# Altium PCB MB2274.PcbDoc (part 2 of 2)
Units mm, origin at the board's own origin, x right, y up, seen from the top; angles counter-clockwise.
Board outline 127 x 73 mm, 4 copper layers (Top Layer, Signal Layer 1, Signal Layer 2, Bottom Layer), stack 1.49 mm thick; 50 components, 79 nets, 284 pads, 1052 vias.
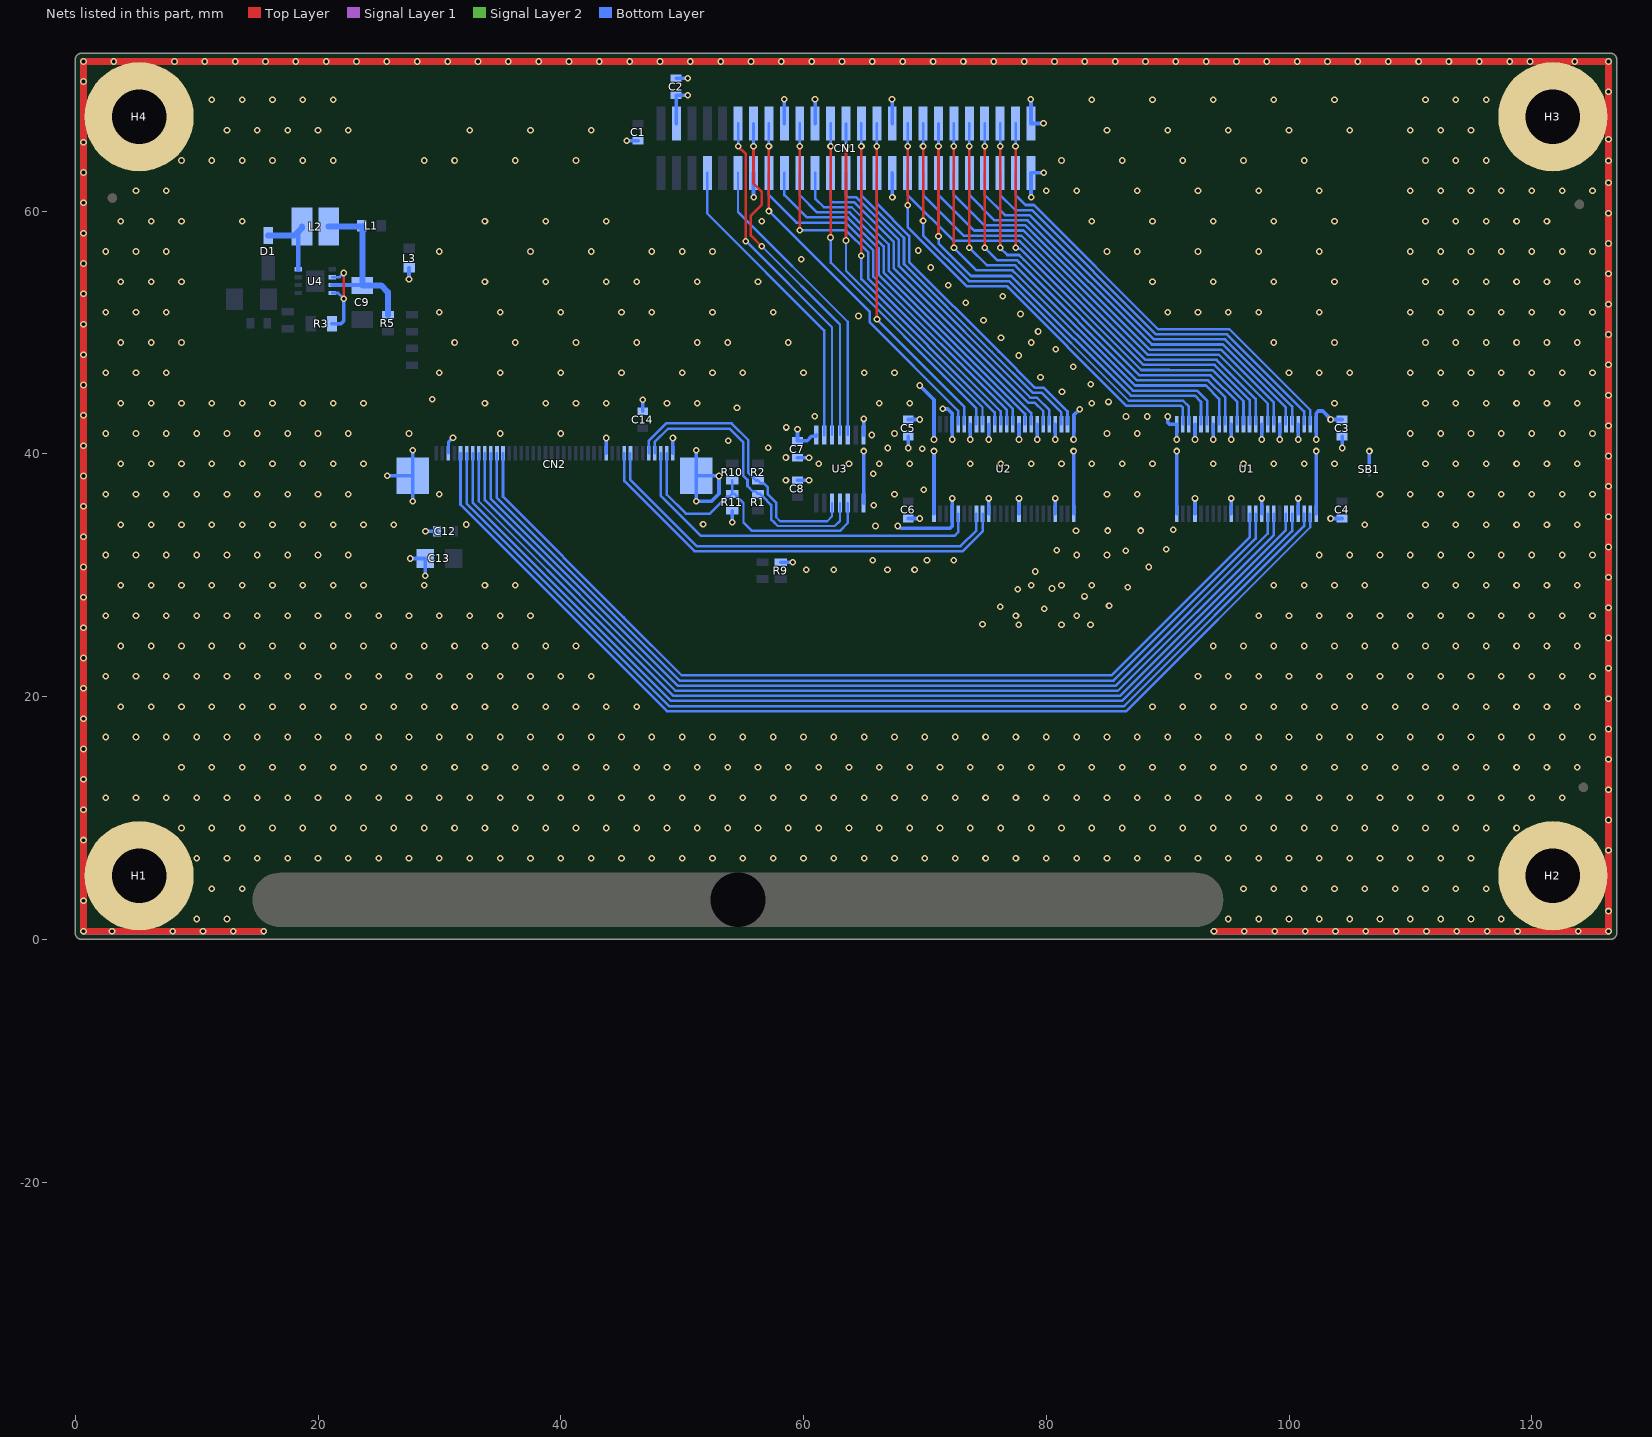
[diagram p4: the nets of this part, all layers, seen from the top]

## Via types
v1: diameter 0.55, hole 0.3, Top Layer to Bottom Layer, 1052 vias

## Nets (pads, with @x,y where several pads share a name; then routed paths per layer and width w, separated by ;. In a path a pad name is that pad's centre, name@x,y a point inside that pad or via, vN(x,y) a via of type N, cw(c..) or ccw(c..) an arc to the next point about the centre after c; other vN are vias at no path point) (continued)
GND: C1.1 C2.1 C3.1 C4.1 C5.1 C6.1 C7.1 C8.1 C12.1 C13.2 C14.1 CN1.1 CN1.2 CN1.19 CN1.20 CN1.30 CN1.34 CN1.37 CN2.1 CN2.12 CN2.38 CN2.MP1 CN2.MP2 H1.1 H2.1 H3.1 H4.1 L3.1 R9.1 R11.1 U1.4 U1.10 U1.15 U1.21 U1.25 U1.28 U1.34 U1.39 U1.45 U1.48 U2.4 U2.10 U2.15 U2.21 U2.25 U2.28 U2.34 U2.39 U2.45 U2.48 U3.7 | length 1377.9
  Top Layer w0.55: H1.1@5.26,5.23 5.375,5.115 5.375,0.997 5.053,0.675 ; v1(15.525,0.675) 5.053,0.675 ; v1(93.825,0.675) v1(108.825,0.675) v1(111.325,0.675) v1(126.325,0.675) v1(126.325,7.325) v1(126.325,9.825) 126.325,11.95 v1(126.325,42.325) v1(126.325,44.825) 126.325,71.43 v1(126.325,72.325) v1(20.675,72.325) v1(0.675,72.325) v1(0.675,28.175) v1(0.675,25.675) v1(0.675,23.175) v1(0.675,20.675) v1(0.675,18.175) v1(0.675,15.675) v1(0.675,13.175) v1(0.675,10.675) v1(0.675,8.175) v1(0.675,3.175) v1(0.675,0.675) 5.053,0.675
  Signal Layer 1 w0.55: H1.1@5.26,5.23 5.375,5.115 5.375,0.997 5.053,0.675 ; v1(15.525,0.675) 5.053,0.675 ; v1(93.825,0.675) v1(108.825,0.675) v1(111.325,0.675) v1(126.325,0.675) v1(126.325,7.325) v1(126.325,9.825) 126.325,11.95 v1(126.325,42.325) v1(126.325,44.825) 126.325,71.43 v1(126.325,72.325) v1(35.675,72.325) v1(0.675,72.325) v1(0.675,28.175) v1(0.675,25.675) v1(0.675,23.175) v1(0.675,20.675) v1(0.675,18.175) v1(0.675,15.675) v1(0.675,13.175) v1(0.675,10.675) v1(0.675,8.175) v1(0.675,3.175) v1(0.675,0.675) 5.053,0.675
  Signal Layer 2 w0.55: H1.1@5.26,5.23 5.375,5.115 5.375,0.997 5.053,0.675 ; v1(15.525,0.675) 5.053,0.675 ; v1(93.825,0.675) v1(108.825,0.675) v1(111.325,0.675) v1(126.325,0.675) v1(126.325,7.325) v1(126.325,9.825) 126.325,11.95 v1(126.325,42.325) v1(126.325,44.825) 126.325,71.43 v1(126.325,72.325) v1(0.675,72.325) v1(0.675,28.175) v1(0.675,25.675) v1(0.675,23.175) v1(0.675,20.675) v1(0.675,18.175) v1(0.675,15.675) v1(0.675,13.175) v1(0.675,10.675) v1(0.675,8.175) v1(0.675,3.175) v1(0.675,0.675) 5.053,0.675
  Bottom Layer w0.25: CN2.38@30.74,40.05 30.74,40.95 v1(31.115,41.325)
  Bottom Layer w0.3: v1(25.7,38.195) 25.705,38.19 CN2.MP2@27.81,38.19 ; v1(27.5,54.375) L3.1@27.5,55.325 ; v1(27.6,31.375) C13.2@28.825,31.375 v1(28.825,29.95) ; v1(27.805,36.08) 27.81,36.085 CN2.MP2@27.81,38.19 ; v1(27.815,40.3) 27.81,40.295 CN2.MP2@27.81,38.19 ; v1(28.85,33.625) C12.1@29.8,33.625 ; CN2.12@43.74,40.05 v1@43.74,41.225 ; v1(45.425,65.8) C1.1@46.375,65.8 ; C14.1@46.75,43.513 v1(46.75,44.463) ; CN2.1@49.24,40.05 v1@49.24,41.225 ; C2.1@49.5,70.95 v1(50.45,70.95) ; v1(51.175,40.3) 51.17,40.295 CN2.MP1@51.17,38.19 ; v1(54.125,34.35) R11.1@54.125,35.3 ; CN1.37@55.88,63.147 55.88,61.154 v1(55.895,61.139) ; R9.1@58.125,31.075 v1(59.11,31.075) ; v1(58.405,69.225) 58.42,69.21 CN1.34@58.42,67.217 ; C8.1@59.5,37.825 v1(60.45,37.825) ; C7.1@59.5,39.675 v1(60.45,39.675) ; v1(60.945,69.225) 60.96,69.21 CN1.30@60.96,67.217 ; U3.7@64.95,41.55 v1@64.95,42.8 ; v1(67.295,69.225) 67.31,69.21 CN1.20@67.31,67.217 ; CN1.19@67.31,63.147 67.31,61.154 v1(67.325,61.139) ; v1(67.775,34.05) 67.843,34.05 68.018,33.875 72.075,33.875 72.25,34.05 U2.21@72.25,35.075 v1(72.25,36.325) ; C6.1@68.625,34.675 v1(69.575,34.675) ; C5.1@68.625,42.825 v1(69.575,42.825) ; v1(69.575,45.625) 70.75,44.45 U2.25@70.75,42.425 v1(70.75,41.175) ; v1(71.475,43.725) 71.507,43.693 71.882,43.693 72.25,43.325 v1(72.25,41.175) ; U2.15@75.25,35.075 v1(75.25,36.325) ; v1(75.25,41.175) U2.34@75.25,42.425 ; U2.10@77.75,35.075 v1(77.75,36.325) ; v1(77.75,41.175) U2.39@77.75,42.425 ; v1(78.725,69.225) 78.74,69.21 CN1.2@78.74,67.217 79.767,67.217 v1(79.775,67.225) ; v1(78.755,61.139) 78.74,61.154 CN1.1@78.74,63.147 79.797,63.147 v1(79.8,63.15) ; U2.4@80.75,35.075 v1(80.75,36.325) ; v1(80.75,41.175) U2.45@80.75,42.425 ; v1(82.25,41.175) U2.48@82.25,42.425 82.25,43.175 v1(82.75,43.675) ; v1(90,43.075) 90,42.574 90.149,42.425 U1.25@90.75,42.425 v1(90.75,41.175) ; U1.21@92.25,35.075 v1(92.25,36.325) ; v1(92.25,41.175) U1.28@92.25,42.425 ; U1.15@95.25,35.075 v1(95.25,36.325) ; v1(95.25,41.175) U1.34@95.25,42.425 ; U1.10@97.75,35.075 v1(97.75,36.325) ; v1(97.75,41.175) U1.39@97.75,42.425 ; U1.4@100.75,35.075 v1(100.75,36.325) ; v1(100.75,41.175) U1.45@100.75,42.425 ; v1(102.25,41.175) U1.48@102.25,42.425 102.25,43.35 102.425,43.525 102.775,43.525 103.425,42.875 v1(103.425,42.825) C3.1@104.375,42.825 ; v1(103.425,34.675) C4.1@104.375,34.675 ; CN2.MP1@51.17,38.19 51.17,36.085 v1(51.165,36.08) 52.405,36.08 53.04,36.715 v1(53.04,38.175) 53.025,38.19 CN2.MP1@51.17,38.19
  Bottom Layer w0.55: H1.1@5.26,5.23 5.375,5.115 5.375,0.997 5.053,0.675 ; v1(15.525,0.675) 5.053,0.675 ; v1(93.825,0.675) v1(108.825,0.675) v1(111.325,0.675) v1(126.325,0.675) v1(126.325,7.325) v1(126.325,9.825) 126.325,11.95 v1(126.325,42.325) v1(126.325,44.825) 126.325,71.43 v1(126.325,72.325) v1(0.675,72.325) v1(0.675,28.175) v1(0.675,25.675) v1(0.675,23.175) v1(0.675,20.675) v1(0.675,18.175) v1(0.675,15.675) v1(0.675,13.175) v1(0.675,10.675) v1(0.675,8.175) v1(0.675,3.175) v1(0.675,0.675) 5.053,0.675
  other v1: 3.025,0.675 8.025,0.675 10.525,0.675 13.025,0.675 96.325,0.675 98.825,0.675 101.325,0.675 103.825,0.675 106.325,0.675 113.825,0.675 116.325,0.675 118.825,0.675 123.825,0.675 10,1.669 12.5,1.669 95,1.669 97.5,1.669 100,1.669 102.5,1.669 105,1.669 107.5,1.669 110,1.669 112.5,1.669 115,1.669 117.5,1.669 126.325,2.325 11.25,4.169 13.75,4.169 96.25,4.169 98.75,4.169 101.25,4.169 103.75,4.169 106.25,4.169 108.75,4.169 111.25,4.169 113.75,4.169 116.25,4.169 10,6.669 12.5,6.669 15,6.669 17.5,6.669 20,6.669 22.5,6.669 25,6.669 27.5,6.669 30,6.669 32.5,6.669 35,6.669 37.5,6.669 40,6.669 42.5,6.669 45,6.669 47.5,6.669 50,6.669 52.5,6.669 55,6.669 57.5,6.669 60,6.669 62.5,6.669 65,6.669 67.5,6.669 70,6.669 72.5,6.669 75,6.669 77.5,6.669 80,6.669 82.5,6.669 85,6.669 87.5,6.669 90,6.669 92.5,6.669 95,6.669 97.5,6.669 100,6.669 102.5,6.669 105,6.669 107.5,6.669 110,6.669 112.5,6.669 115,6.669 8.75,9.169 11.25,9.169 13.75,9.169 16.25,9.169 18.75,9.169 21.25,9.169 23.75,9.169 26.25,9.169 28.75,9.169 31.25,9.169 33.75,9.169 36.25,9.169 38.75,9.169 41.25,9.169 43.75,9.169 46.25,9.169 48.75,9.169 51.25,9.169 53.75,9.169 56.25,9.169 58.75,9.169 61.25,9.169 63.75,9.169 66.25,9.169 68.75,9.169 71.25,9.169 73.75,9.169 76.25,9.169 78.75,9.169 81.25,9.169 83.75,9.169 86.25,9.169 88.75,9.169 91.25,9.169 93.75,9.169 96.25,9.169 98.75,9.169 101.25,9.169 103.75,9.169 106.25,9.169 108.75,9.169 111.25,9.169 113.75,9.169 116.25,9.169 118.75,9.169 2.5,11.669 5,11.669 7.5,11.669 10,11.669 12.5,11.669 15,11.669 17.5,11.669 20,11.669 22.5,11.669 25,11.669 27.5,11.669 30,11.669 32.5,11.669 35,11.669 37.5,11.669 40,11.669 42.5,11.669 45,11.669 47.5,11.669 50,11.669 52.5,11.669 55,11.669 57.5,11.669 60,11.669 62.5,11.669 65,11.669 67.5,11.669 70,11.669 72.5,11.669 75,11.669 77.5,11.669 80,11.669 82.5,11.669 85,11.669 87.5,11.669 90,11.669 92.5,11.669 95,11.669 97.5,11.669 100,11.669 102.5,11.669 105,11.669 107.5,11.669 110,11.669 112.5,11.669 115,11.669 117.5,11.669 120,11.669 122.5,11.669 126.325,12.325 8.75,14.169 11.25,14.169 13.75,14.169 16.25,14.169 18.75,14.169 21.25,14.169 23.75,14.169 26.25,14.169 28.75,14.169 31.25,14.169 33.75,14.169 36.25,14.169 38.75,14.169 41.25,14.169 43.75,14.169 46.25,14.169 48.75,14.169 51.25,14.169 53.75,14.169 56.25,14.169 58.75,14.169 61.25,14.169 63.75,14.169 66.25,14.169 68.75,14.169 71.25,14.169 73.75,14.169 76.25,14.169 78.75,14.169 81.25,14.169 83.75,14.169 86.25,14.169 88.75,14.169 91.25,14.169 93.75,14.169 96.25,14.169 98.75,14.169 101.25,14.169 103.75,14.169 106.25,14.169 108.75,14.169 111.25,14.169 113.75,14.169 116.25,14.169 118.75,14.169 121.25,14.169 123.75,14.169 126.325,14.825 2.5,16.669 5,16.669 7.5,16.669 10,16.669 12.5,16.669 15,16.669 17.5,16.669 20,16.669 22.5,16.669 25,16.669 27.5,16.669 30,16.669 32.5,16.669 35,16.669 37.5,16.669 40,16.669 42.5,16.669 45,16.669 47.5,16.669 50,16.669 52.5,16.669 55,16.669 57.5,16.669 60,16.669 62.5,16.669 65,16.669 67.5,16.669 70,16.669 72.5,16.669 75,16.669 77.5,16.669 80,16.669 82.5,16.669 85,16.669 87.5,16.669 90,16.669 92.5,16.669 95,16.669 97.5,16.669 100,16.669 102.5,16.669 105,16.669 107.5,16.669 110,16.669 112.5,16.669 115,16.669 117.5,16.669 120,16.669 122.5,16.669 125,16.669 126.325,17.325 3.75,19.169 6.25,19.169 8.75,19.169 11.25,19.169 13.75,19.169 16.25,19.169 18.75,19.169 21.25,19.169 23.75,19.169 26.25,19.169 28.75,19.169 31.25,19.169 33.75,19.169 36.25,19.169 38.75,19.169 41.25,19.169 43.75,19.169 46.25,19.169 88.75,19.169 91.25,19.169 93.75,19.169 96.25,19.169 98.75,19.169 101.25,19.169 103.75,19.169 106.25,19.169 108.75,19.169 111.25,19.169 113.75,19.169 116.25,19.169 118.75,19.169 121.25,19.169 123.75,19.169 126.325,19.825 2.5,21.669 5,21.669 7.5,21.669 10,21.669 12.5,21.669 15,21.669 17.5,21.669 20,21.669 22.5,21.669 25,21.669 27.5,21.669 30,21.669 32.5,21.669 35,21.669 37.5,21.669 40,21.669 42.5,21.669 92.5,21.669 95,21.669 97.5,21.669 100,21.669 102.5,21.669 105,21.669 107.5,21.669 110,21.669 112.5,21.669 115,21.669 117.5,21.669 120,21.669 122.5,21.669 125,21.669 126.325,22.325 3.75,24.169 6.25,24.169 8.75,24.169 11.25,24.169 13.75,24.169 16.25,24.169 18.75,24.169 21.25,24.169 23.75,24.169 26.25,24.169 28.75,24.169 31.25,24.169 33.75,24.169 36.25,24.169 38.75,24.169 41.25,24.169 93.75,24.169 96.25,24.169 98.75,24.169 101.25,24.169 103.75,24.169 106.25,24.169 108.75,24.169 111.25,24.169 113.75,24.169 116.25,24.169 118.75,24.169 121.25,24.169 123.75,24.169 126.325,24.825 77.725,25.925 81.25,25.925 83.65,25.925 74.75,25.95 2.5,26.669 5,26.669 7.5,26.669 10,26.669 12.5,26.669 15,26.669 17.5,26.669 20,26.669 22.5,26.669 25,26.669 27.5,26.669 30,26.669 32.5,26.669 35,26.669 37.5,26.669 77.5,26.669 82.5,26.669 97.5,26.669 100,26.669 102.5,26.669 105,26.669 107.5,26.669 110,26.669 112.5,26.669 115,26.669 117.5,26.669 120,26.669 122.5,26.669 125,26.669 79.835,27.236 126.325,27.325 76.2,27.4 85.175,27.475 83.15,28.25 77.65,28.85 80.475,28.9 86.725,29 3.75,29.169 6.25,29.169 8.75,29.169 11.25,29.169 13.75,29.169 16.25,29.169 18.75,29.169 21.25,29.169 23.75,29.169 28.75,29.169 33.75,29.169 36.25,29.169 78.75,29.169 81.25,29.169 83.75,29.169 98.75,29.169 101.25,29.169 103.75,29.169 106.25,29.169 111.25,29.169 113.75,29.169 116.25,29.169 118.75,29.169 121.25,29.169 123.75,29.169 126.325,29.825 79.1,30.3 60.225,30.45 62.5,30.45 66.925,30.45 69.15,30.45 0.675,30.675 88.45,30.675 65.7,31.225 70.175,31.225 72.375,31.225 2.5,31.669 5,31.669 7.5,31.669 10,31.669 12.5,31.669 15,31.669 17.5,31.669 20,31.669 22.5,31.669 82.5,31.669 85,31.669 102.5,31.669 105,31.669 107.5,31.669 110,31.669 112.5,31.669 115,31.669 117.5,31.669 120,31.669 122.5,31.669 125,31.669 86.55,32.025 80.875,32.05 89.875,32.125 126.325,32.325 0.675,33.175 82.45,33.65 85.075,33.675 87.775,33.675 90.45,33.75 65.925,34.05 3.75,34.169 6.25,34.169 8.75,34.169 11.25,34.169 13.75,34.169 16.25,34.169 18.75,34.169 21.25,34.169 23.75,34.169 26.25,34.169 32.2,34.175 106.25,34.169 111.25,34.169 113.75,34.169 116.25,34.169 118.75,34.169 121.25,34.169 123.75,34.169 51.725,34.2 126.325,34.825 0.675,35.675 65.775,35.775 2.5,36.669 5,36.669 7.5,36.669 10,36.669 12.5,36.669 15,36.669 17.5,36.669 20,36.669 22.5,36.669 30,36.669 67.5,36.669 85,36.669 87.5,36.669 107.5,36.669 110,36.669 112.5,36.669 115,36.669 117.5,36.669 120,36.669 122.5,36.669 125,36.669 69.9,37.05 126.325,37.325 58.55,37.825 0.675,38.175 65.75,38.35 3.75,39.169 6.25,39.169 8.75,39.169 11.25,39.169 13.75,39.169 16.25,39.169 18.75,39.169 21.25,39.169 23.75,39.169 61.25,39.169 63.75,39.169 66.25,39.169 68.75,39.169 73.75,39.169 76.25,39.169 78.75,39.169 81.25,39.169 83.75,39.169 86.25,39.169 88.75,39.169 93.75,39.169 96.25,39.169 98.75,39.169 101.25,39.169 103.75,39.169 111.25,39.169 113.75,39.169 116.25,39.169 118.75,39.169 121.25,39.169 123.75,39.169 58.55,39.7 126.325,39.825 69.775,40.425 66.95,40.475 57.1,40.5 0.675,40.675 53.8,41.075 43.74,41.3 49.24,41.3 65.625,41.55 2.5,41.669 5,41.669 7.5,41.669 10,41.669 12.5,41.669 15,41.669 17.5,41.669 20,41.669 22.5,41.669 27.5,41.669 35,41.669 40,41.669 67.5,41.669 85,41.669 87.5,41.669 110,41.669 112.5,41.669 115,41.669 117.5,41.669 120,41.669 122.5,41.669 125,41.669 58.575,42.175 64.95,42.875 86.575,43.075 88.325,43.075 60.925,43.1 0.675,43.175 54.525,43.8 3.75,44.169 6.25,44.169 8.75,44.169 11.25,44.169 13.75,44.169 16.25,44.169 18.75,44.169 21.25,44.169 23.75,44.169 33.75,44.169 38.75,44.169 41.25,44.169 43.75,44.169 48.75,44.169 51.25,44.169 66.25,44.169 68.75,44.169 83.75,44.169 103.75,44.169 111.25,44.169 113.75,44.169 116.25,44.169 118.75,44.169 121.25,44.169 123.75,44.169 85.125,44.275 29.4,44.5 81.3,45.125 0.675,45.675 83.675,45.725 79.525,46.3 2.5,46.669 5,46.669 7.5,46.669 30,46.669 35,46.669 40,46.669 45,46.669 50,46.669 52.5,46.669 55,46.669 60,46.669 65,46.669 67.5,46.669 100,46.669 102.5,46.669 105,46.669 110,46.669 112.5,46.669 115,46.669 117.5,46.669 120,46.669 122.5,46.669 125,46.669 82.225,47.175 126.325,47.325 77.725,48.1 0.675,48.175 80.775,48.625 3.75,49.169 6.25,49.169 8.75,49.169 31.25,49.169 36.25,49.169 41.25,49.169 46.25,49.169 51.25,49.169 53.75,49.169 58.75,49.169 78.75,49.169 98.75,49.169 103.75,49.169 111.25,49.169 113.75,49.169 116.25,49.169 118.75,49.169 121.25,49.169 123.75,49.169 76.275,49.55 126.325,49.825 79.325,50.075 0.675,50.675 74.825,51 64.525,51.35 77.875,51.525 2.5,51.669 5,51.669 7.5,51.669 30,51.669 35,51.669 40,51.669 45,51.669 47.5,51.669 52.5,51.669 57.5,51.669 90,51.669 92.5,51.669 95,51.669 97.5,51.669 102.5,51.669 110,51.669 112.5,51.669 115,51.669 117.5,51.669 120,51.669 122.5,51.669 125,51.669 126.325,52.325 73.375,52.45 76.425,52.975 0.675,53.175 71.925,53.9 3.75,54.169 6.25,54.169 8.75,54.169 33.75,54.169 38.75,54.169 43.75,54.169 46.25,54.169 51.25,54.169 56.25,54.169 88.75,54.169 93.75,54.169 98.75,54.169 103.75,54.169 111.25,54.169 113.75,54.169 116.25,54.169 118.75,54.169 121.25,54.169 123.75,54.169 126.325,54.825 70.475,55.35 0.675,55.675 59.8,56.025 2.5,56.669 5,56.669 7.5,56.669 30,56.669 37.5,56.669 42.5,56.669 47.5,56.669 50,56.669 52.5,56.669 85,56.669 87.5,56.669 92.5,56.669 97.5,56.669 102.5,56.669 110,56.669 112.5,56.669 115,56.669 117.5,56.669 120,56.669 122.5,56.669 125,56.669 69.45,56.75 126.325,57.325 0.675,58.175 56.55,59.15 3.75,59.169 6.25,59.169 8.75,59.169 13.75,59.169 33.75,59.169 38.75,59.169 43.75,59.169 83.75,59.169 88.75,59.169 93.75,59.169 98.75,59.169 103.75,59.169 111.25,59.169 113.75,59.169 116.25,59.169 118.75,59.169 121.25,59.169 126.325,59.825 0.675,60.675 5,61.669 7.5,61.669 80,61.669 82.5,61.669 87.5,61.669 92.5,61.669 97.5,61.669 102.5,61.669 110,61.669 112.5,61.669 115,61.669 117.5,61.669 120,61.669 122.5,61.669 125,61.669 126.325,62.325 0.675,63.175 126.325,64.15 8.75,64.169 11.25,64.169 13.75,64.169 16.25,64.169 18.75,64.169 21.25,64.169 28.75,64.169 31.25,64.169 36.25,64.169 41.25,64.169 81.25,64.169 86.25,64.169 91.25,64.169 96.25,64.169 101.25,64.169 111.25,64.169 113.75,64.169 116.25,64.169 0.675,65.675 126.325,65.925 12.5,66.669 15,66.669 17.5,66.669 20,66.669 22.5,66.669 32.5,66.669 37.5,66.669 42.5,66.669 85,66.669 90,66.669 95,66.669 100,66.669 105,66.669 110,66.669 112.5,66.669 115,66.669 11.25,69.169 13.75,69.169 16.25,69.169 18.75,69.169 21.25,69.169 83.75,69.169 88.75,69.169 93.75,69.169 98.75,69.169 103.75,69.169 111.25,69.169 113.75,69.169 116.25,69.169 126.325,69.825 0.675,70.675 3.175,72.325 8.175,72.325 10.675,72.325 13.175,72.325 15.675,72.325 18.175,72.325 23.175,72.325 25.675,72.325 28.175,72.325 30.675,72.325 33.175,72.325 38.175,72.325 40.675,72.325 43.175,72.325 45.675,72.325 48.175,72.325 50.675,72.325 53.175,72.325 55.675,72.325 58.175,72.325 60.675,72.325 63.175,72.325 65.675,72.325 68.175,72.325 70.675,72.325 73.175,72.325 75.675,72.325 78.175,72.325 80.675,72.325 83.175,72.325 85.675,72.325 88.175,72.325 90.675,72.325 93.175,72.325 95.675,72.325 98.175,72.325 100.675,72.325 103.175,72.325 105.675,72.325 108.175,72.325 110.675,72.325 113.175,72.325 115.675,72.325 118.175,72.325 119.85,72.325 123.55,72.325
HOST_B0: CN1.21 U2.47 | length 27.7
  Bottom Layer w0.21: CN1.21@66.04,63.147 66.04,60.621 68.7,57.961 68.7,55.805 76.092,48.414 79.045,45.46 79.784,45.46 81.75,43.494 U2.47@81.75,42.425
HOST_B1: CN1.23 U2.46 | length 28
  Bottom Layer w0.21: CN1.23@64.77,63.147 64.77,61.297 68.28,57.787 68.28,55.631 75.502,48.409 78.871,45.04 79.61,45.04 81.25,43.4 U2.46@81.25,42.425
HOST_B2: CN1.25 U2.44 | length 28.4
  Bottom Layer w0.21: CN1.25@63.5,63.147 63.5,61.277 63.623,61.154 64.32,61.154 67.86,57.613 67.86,55.457 78.697,44.62 79.24,44.62 80.25,43.61 U2.44@80.25,42.425
HOST_B3: CN1.27 U2.43 | length 29.3
  Bottom Layer w0.21: CN1.27@62.23,63.147 62.23,60.857 62.353,60.734 64.146,60.734 67.44,57.439 67.44,55.283 78.523,44.2 79.066,44.2 79.75,43.516 U2.43@79.75,42.425
HOST_B4: CN1.29 U2.41 | length 29.4
  Bottom Layer w0.21: CN1.29@60.96,63.147 60.96,61.028 61.674,60.314 63.972,60.314 67.02,57.265 67.02,55.109 78.75,43.379 U2.41@78.75,42.425
HOST_B5: CN1.31 U2.40 | length 30
  Bottom Layer w0.21: CN1.31@59.69,63.147 59.69,61.325 61.121,59.894 63.798,59.894 66.6,57.091 66.6,54.935 78.25,43.285 U2.40@78.25,42.425
HOST_B6: CN1.33 U2.38 | length 30.5
  Bottom Layer w0.21: CN1.33@58.42,63.147 58.42,61.325 60.271,59.474 63.624,59.474 66.18,56.917 66.18,54.762 77.25,43.692 U2.38@77.25,42.425
HOST_B7: CN1.35 U2.37 | length 31.2
  Bottom Layer w0.21: CN1.35@57.15,63.147 57.15,61.325 59.421,59.054 63.45,59.054 65.76,56.743 65.76,54.588 76.75,43.598 U2.37@76.75,42.425
HOST_BL_CTRL: CN1.43 U3.2 | length 25.6
  Bottom Layer w0.21: CN1.43@52.07,63.147 52.07,59.805 61.7,50.175 U3.2@61.7,41.55
HOST_CLK: CN1.32 U2.36 | length 33.9
  Top Layer w0.21: v1(59.69,65.337) 59.69,58.435 v1(59.7,58.425)
  Bottom Layer w0.21: v1(59.69,65.337) CN1.32@59.69,67.217 ; v1(59.7,58.425) 62.375,58.425 62.385,58.415 63.494,58.415 65.34,56.569 65.34,54.414 76.25,43.504 U2.36@76.25,42.425
HOST_DE: CN1.22 U2.30 | length 27.8
  Top Layer w0.21: v1(66.04,65.337) 66.04,51.085 v1(66.05,51.075)
  Bottom Layer w0.21: v1(66.04,65.337) CN1.22@66.04,67.217 ; v1(66.05,51.075) 73.25,43.875 U2.30@73.25,42.425
HOST_DISP: CN1.24 U2.35 | length 29.4
  Top Layer w0.21: v1(64.75,56.325) 64.77,56.345 v1(64.77,65.337)
  Bottom Layer w0.21: v1(64.75,56.325) 64.762,56.313 64.762,54.398 75.75,43.41 U2.35@75.75,42.425 ; v1(64.77,65.337) CN1.24@64.77,67.217
HOST_G0: CN1.4 U1.36 | length 36.2
  Top Layer w0.21: v1(77.47,65.337) 77.47,56.975 v1(77.475,56.97)
  Bottom Layer w0.21: v1(77.47,65.337) CN1.4@77.47,67.217 ; v1(77.475,56.97) 77.539,56.906 77.825,56.906 87.826,46.905 90.151,46.905 ; 90.151,46.89 93.705,46.89 96.25,44.345 U1.36@96.25,42.425
HOST_G1: CN1.6 U1.35 | length 36.9
  Top Layer w0.21: v1@76.2,56.975 v1(76.2,65.337)
  Bottom Layer w0.21: v1(76.2,65.337) CN1.6@76.2,67.217 ; v1(76.205,56.97) 76.795,56.38 77.757,56.38 78.148,55.989 87.667,46.47 93.531,46.47 95.75,44.251 U1.35@95.75,42.425
HOST_G2: CN1.8 U1.33 | length 37.4
  Top Layer w0.21: v1@74.93,56.975 v1(74.93,65.337)
  Bottom Layer w0.21: v1(74.93,65.337) CN1.8@74.93,67.217 ; v1(74.935,56.97) 75.945,55.96 77.583,55.96 77.78,55.764 87.493,46.05 93.325,46.05 94.75,44.625 U1.33@94.75,42.425
HOST_G3: CN1.10 U1.32 | length 38.1
  Top Layer w0.21: v1@73.66,56.975 v1(73.66,65.337)
  Bottom Layer w0.21: v1(73.66,65.337) CN1.10@73.66,67.217 ; v1(73.665,56.97) 75.095,55.54 77.409,55.54 77.606,55.344 77.708,55.241 87.319,45.63 93.151,45.63 94.25,44.531 U1.32@94.25,42.425
HOST_G4: CN1.12 U1.30 | length 38.3
  Top Layer w0.21: v1@72.39,56.975 v1(72.39,65.337)
  Bottom Layer w0.21: v1(72.39,65.337) CN1.12@72.39,67.217 ; v1(72.395,56.97) 74.245,55.12 77.235,55.12 77.768,54.587 87.145,45.21 92.414,45.21 93.25,44.374 U1.30@93.25,42.425
HOST_G5: CN1.14 U1.29 | length 38.8
  Top Layer w0.21: v1(71.12,65.337) 71.12,57.93 v1(71.125,57.925)
  Bottom Layer w0.21: v1(71.12,65.337) CN1.14@71.12,67.217 ; v1(71.125,57.925) 71.125,57.325 73.8,54.65 77.111,54.65 77.594,54.167 86.971,44.79 92.24,44.79 92.75,44.28 U1.29@92.75,42.425
HOST_G6: CN1.16 U1.27 | length 38.4
  Top Layer w0.21: v1(69.85,59.2) v1(69.85,65.337)
  Bottom Layer w0.21: v1(69.85,59.2) 69.85,58 73.62,54.23 76.937,54.23 77.42,53.747 86.797,44.37 91.275,44.37 91.75,43.895 U1.27@91.75,42.425 ; v1(69.85,65.337) CN1.16@69.85,67.217
HOST_G7: CN1.18 U1.26 | length 38.8
  Top Layer w0.21: v1(68.575,60.475) 68.58,60.48 v1(68.58,65.337)
  Bottom Layer w0.21: v1(68.575,60.475) 68.575,58.681 73.446,53.81 76.763,53.81 76.887,53.687 86.623,43.95 91.101,43.95 91.251,43.801 U1.26@91.251,42.426 ; v1(68.58,65.337) CN1.18@68.58,67.217
HOST_HSYNC: CN1.26 U2.33 | length 29.5
  Top Layer w0.21: v1(63.5,57.575) v1(63.5,65.337)
  Bottom Layer w0.19: v1(63.5,57.575) 63.5,55.08 74.75,43.83 U2.33@74.75,42.425
  Bottom Layer w0.21: v1(63.5,65.337) CN1.26@63.5,67.217
HOST_INT: CN1.39 U3.5 | length 25.3
  Bottom Layer w0.19: CN1.39@54.6,63.147 54.6,59.925 63.65,50.875 U3.5@63.65,41.55
HOST_R0: CN1.3 U1.47 | length 34.6
  Bottom Layer w0.21: CN1.3@77.47,63.147 77.47,61.325 78.295,60.5 78.983,60.5 89.218,50.265 95.082,50.265 101.75,43.597 U1.47@101.75,42.425
HOST_R1: CN1.5 U1.46 | length 35.3
  Bottom Layer w0.21: CN1.5@76.2,63.147 76.2,61.325 77.445,60.08 78.809,60.08 89.044,49.845 94.908,49.845 101.25,43.503 U1.46@101.25,42.425
HOST_R2: CN1.7 U1.44 | length 35.8
  Bottom Layer w0.21: CN1.7@74.93,63.147 74.93,61.325 76.595,59.66 78.635,59.66 88.87,49.425 94.734,49.425 100.25,43.909 U1.44@100.25,42.425
HOST_R3: CN1.9 U1.43 | length 36.6
  Bottom Layer w0.21: CN1.9@73.66,63.147 73.66,61.325 75.745,59.24 78.461,59.24 88.696,49.005 94.56,49.005 99.75,43.815 U1.43@99.75,42.425
HOST_R4: CN1.11 U1.41 | length 37.1
  Bottom Layer w0.21: CN1.11@72.39,63.147 72.39,61.325 74.895,58.82 78.287,58.82 88.522,48.585 94.386,48.585 98.75,44.221 U1.41@98.75,42.425
HOST_R5: CN1.13 U1.40 | length 37.8
  Bottom Layer w0.21: CN1.13@71.12,63.147 71.12,61.325 74.045,58.4 78.113,58.4 88.348,48.165 94.212,48.165 98.25,44.127 U1.40@98.25,42.425
HOST_R6: CN1.15 U1.38 | length 38.3
  Bottom Layer w0.21: CN1.15@69.85,63.147 69.85,61.325 73.195,57.98 77.939,57.98 88.174,47.745 94.038,47.745 97.25,44.533 U1.38@97.25,42.425
HOST_R7: CN1.17 U1.37 | length 39
  Bottom Layer w0.21: CN1.17@68.58,63.147 68.58,61.325 72.345,57.56 77.765,57.56 88,47.325 93.864,47.325 96.75,44.439 U1.37@96.75,42.425
HOST_RST: CN1.36 U2.29 | length 31.3
  Top Layer w0.21: v1(57.15,60) v1(57.15,65.337)
  Bottom Layer w0.21: v1(57.15,60) 65.46,51.69 65.46,50.831 72.75,43.541 U2.29@72.75,42.425 ; v1(57.15,65.337) CN1.36@57.15,67.217
HOST_SCL: CN1.40 U3.3 | length 28.9
  Top Layer w0.21: v1(54.61,65.337) 55.25,64.697 v1(55.25,57.525)
  Bottom Layer w0.19: v1(55.25,57.525) 62.35,50.425 U3.3@62.35,41.55
  Bottom Layer w0.21: v1(54.61,65.337) CN1.40@54.61,67.217
HOST_SDA: CN1.38 U3.4 | length 29.3
  Top Layer w0.21: v1(55.88,65.337) 55.88,62.272 56.55,61.602 56.55,60.505 55.67,59.625 55.67,57.98 v1(56.55,57.1)
  Bottom Layer w0.19: v1(56.55,57.1) 63,50.65 U3.4@63,41.55
  Bottom Layer w0.21: v1(55.88,65.337) CN1.38@55.88,67.217
HOST_VSYNC: CN1.28 U2.32 | length 29.8
  Top Layer w0.21: v1(62.225,57.825) 62.23,57.83 v1(62.23,65.337)
  Bottom Layer w0.21: v1(62.225,57.825) 62.245,57.805 62.245,55.755 74.25,43.75 U2.32@74.25,42.425 ; v1(62.23,65.337) CN1.28@62.23,67.217
HSYNC: CN2.9 U2.16 | length 36.3
  Bottom Layer w0.21: CN2.9@45.24,40.05 45.24,37.753 51.013,31.98 73.124,31.98 74.75,33.606 U2.16@74.75,35.075
INT: CN2.2 R10.1 R11.2 U3.10 | length 24.9
  Bottom Layer w0.19: R11.2@54.125,36.7 54.305,36.7 55.05,35.955 55.05,34.35 55.75,33.65 63,33.65 63.65,34.3 U3.10@63.65,35.95
  Bottom Layer w0.21: CN2.2@48.74,40.05 48.74,36.629 50.299,35.07 52.29,35.07 53.705,36.485 53.91,36.485 R11.2@54.125,36.7 R10.1@54.125,37.8
NetD1_1: D1.1 L2.2 U4.8 | length 6.2
  Bottom Layer w0.4: U4.8@18.375,55.2 L2.2@18.375,58.29
  Bottom Layer w0.5: D1.1@15.9,57.99 18.075,57.99 18.375,58.29 18.675,58.59 L2.2@18.675,58.725
NetR3_2: R3.2 U4.2 U4.4 | length 7.3
  Top Layer w0.21: v1(22.125,52.775) v1(22.125,54.9)
  Bottom Layer w0.21: U4.4@21.175,53.25 21.65,53.25 v1(22.125,52.775) ; U4.2@21.175,54.55 21.775,54.55 v1(22.125,54.9)
  Bottom Layer w0.3: R3.2@21.15,50.725 21.9,50.725 22.125,50.95 v1(22.125,52.775)
R0: CN2.36 U1.2 | length 88.7
  Bottom Layer w0.21: CN2.36@31.74,40.05 31.74,35.81 48.75,18.8 86.6,18.8 101.75,33.95 U1.2@101.75,35.075
R1: CN2.35 U1.3 | length 87.2
  Bottom Layer w0.21: CN2.35@32.24,40.05 32.24,35.904 48.924,19.22 85.65,19.22 86.426,19.22 101.249,34.043 U1.3@101.25,35.075
R2: CN2.34 U1.5 | length 85.6
  Bottom Layer w0.21: CN2.34@32.74,40.05 32.74,35.998 49.098,19.64 85.476,19.64 86.252,19.64 100.25,33.638 U1.5@100.25,35.075
R3: CN2.33 U1.6 | length 84.1
  Bottom Layer w0.21: CN2.33@33.24,40.05 33.24,36.092 44.416,24.916 49.272,20.06 85.302,20.06 86.078,20.06 99.745,33.727 99.745,35.07 U1.6@99.75,35.075
R4: CN2.32 U1.8 | length 82.4
  Bottom Layer w0.21: CN2.32@33.74,40.05 33.74,36.186 49.446,20.48 85.128,20.48 85.904,20.48 98.75,33.326 U1.8@98.75,35.075
R5: CN2.31 U1.9 | length 81
  Bottom Layer w0.21: CN2.31@34.24,40.05 34.24,36.28 49.62,20.9 84.954,20.9 85.73,20.9 98.25,33.42 U1.9@98.25,35.075
R6: CN2.30 U1.11 | length 79.3
  Bottom Layer w0.21: CN2.30@34.74,40.05 34.74,36.374 49.794,21.32 84.78,21.32 85.556,21.32 97.25,33.014 U1.11@97.25,35.075
R7: CN2.29 U1.12 | length 77.9
  Bottom Layer w0.21: CN2.29@35.24,40.05 35.24,36.468 45.185,26.523 49.968,21.74 84.606,21.74 85.382,21.74 96.75,33.108 U1.12@96.75,35.075
RST: CN2.3 U2.20 | length 31
  Bottom Layer w0.21: CN2.3@48.24,40.05 48.24,36.535 51.535,33.24 72.446,33.24 72.75,33.544 U2.20@72.75,35.075
SCL: CN2.5 R2.1 U3.12 | length 23.9
  Bottom Layer w0.19: 57.745,34.774 58.069,34.45 61.95,34.45 62.35,34.85 U3.12@62.35,35.95
  Bottom Layer w0.21: CN2.5@47.24,40.05 47.24,41.059 48.681,42.5 54.075,42.5 55.445,41.13 55.445,38.425 56.07,37.8 R2.1@56.25,37.8 56.465,37.585 56.69,37.585 57.065,37.21 57.065,36.652 57.745,35.972 57.745,34.774
SDA: CN2.4 R1.1 U3.11 | length 24.2
  Bottom Layer w0.19: 57.595,34.33 57.875,34.05 62.575,34.05 63,34.475 U3.11@63,35.95
  Bottom Layer w0.21: CN2.4@47.74,40.05 47.74,40.965 48.855,42.08 53.901,42.08 55.025,40.956 55.025,38.206 55.383,37.848 55.383,37.342 55.81,36.915 56.035,36.915 R1.1@56.25,36.7 56.43,36.7 56.645,36.485 56.645,36.478 57.325,35.798 57.325,34.6 57.595,34.33
VDD: C2.2 C3.2 C5.2 C7.2 CN1.48 SB1.1 U1.1 U1.24 U1.31 U1.42 U2.1 U2.24 U2.31 U2.42 U3.1 U3.8 | length 39.1
  Bottom Layer w0.3: CN1.48@49.5,67.217 C2.2@49.5,69.55 v1(50.45,69.55) ; v1(59.5,42.025) C7.2@59.5,41.075 60.3,41.075 60.664,41.439 61.025,41.439 61.05,41.464 U3.1@61.05,41.55 ; U3.8@64.95,35.95 v1(64.95,40.225) ; v1(68.625,40.475) C5.2@68.625,41.425 ; U2.24@70.75,35.075 v1(70.75,40.225) ; v1(73.75,41.175) U2.31@73.75,42.425 ; v1(79.25,41.175) U2.42@79.25,42.425 ; U2.1@82.25,35.075 v1(82.25,40.225) ; U1.24@90.75,35.075 v1(90.75,40.225) ; v1(93.75,41.175) U1.31@93.75,42.425 ; v1(99.25,41.175) U1.42@99.25,42.425 ; U1.1@102.25,35.075 v1(102.25,40.225) ; v1(104.375,40.475) C3.2@104.375,41.425 ; 106.625,39.073 SB1.1@106.625,39.2 v1(106.625,40.225) v1@106.625,40.323
VL: C9.2 L1.2 L2.1 R5.1 U4.3 | length 14.3
  Bottom Layer w0.35: U4.3@21.175,53.9 C9.2@23.625,53.9
  Bottom Layer w0.5: L2.1@20.875,58.725 L1.2@23.65,58.725 ; C9.2@23.65,53.875 25.2,53.875 25.75,53.325 R5.1@25.75,51.45 ; C9.2@23.65,53.9 L1.2@23.65,58.725 ; L1.2@23.65,58.775 L1.2@23.65,58.725
VSYNC: CN2.8 U2.17 | length 34.9
  Bottom Layer w0.21: CN2.8@45.74,40.05 45.74,37.847 51.187,32.4 72.95,32.4 74.25,33.7 U2.17@74.25,35.075
pads on no net: CART-1.1 CN1.41 CN1.42 CN1.44 CN1.46 MIRE1.1 MIRE2.1 MIRE3.1 MIRE4.1 MIRE5.1 MIRE6.1 U2.22 U2.23 U2.26 U2.27 U3.6 U3.9

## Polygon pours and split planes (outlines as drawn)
GND on Top Layer "NONET_L-01_P-001" (solid, remove dead copper, pour order 0): 0,73 0,0 127,0 127,73
BLGND on Signal Layer 2 "NONET_L-01_P-001" (solid, remove dead copper, pour order 8): 27.25,53.25 30.75,53.25 34.5,57 49.25,57 50,57.75 50,61.25 49.5,61.75 12,61.75 11,60.75 11,47.75 12,46.75 24.25,46.75 26.75,49.25 26.75,52.75
GND on Signal Layer 2 "NONET_L-01_P-001" (solid, remove dead copper, pour order 3): 44.75,73 44.75,63.25 60.25,63.25 60.25,73
GND on Signal Layer 2 "NONET_L-01_P-001" (solid, remove dead copper, pour order 2): 10.98,63.23 9.25,61.5 9.25,46.75 11,45 25,45 35.25,55.25 50.25,55.25 51.5,56.5 51.5,63.25 51.52,63.23 51.52,72.98 51.5,73 127,73 127,0 126.982,-0.018 0.018,-0.018 0,0 0,73 49.5,73 49.5,63.23
+3V3 on Signal Layer 1 "NONET_L-01_P-001" (solid, remove dead copper, pour order 5): 106.5,38 107,37.5 107,30 106.5,29.5 28.5,29.5 27,31 27,66.75 29.375,69.125 44.625,69.125 45.725,68.025 45.725,52.275 60,38 66.5,38
GND on Signal Layer 1 "NONET_L-01_P-001" (solid, remove dead copper, pour order 6): 25,30.5 25,57.5 23.25,59.25 23.25,68.5 27.5,72.75 27.5,73 16.5,73 0,73 0,0 127,0 127,73 108.5,73 106.246,73 106.246,72.754 108.5,70.5 108.5,29 107.5,28 27.5,28
VDD on Signal Layer 1 "NONET_L-01_P-001" (solid, remove dead copper, pour order 4): 107,40 106.5,39.5 60.5,39.5 47.125,52.875 47.125,68.125 49.5,70.5 106.5,70.5 107,70
GND on Bottom Layer "NONET_L-01_P-001" (solid, remove dead copper, pour order 7): 0,73 0,0 127,0 127,73

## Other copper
Top Layer:
  text "1" at 2.259,13.717 h2
Signal Layer 1:
  text "2" at 3.509,13.717 h2
Signal Layer 2:
  text "3" at 5.009,13.717 h2
Bottom Layer:
  pour cut-out: 16.25,60.75 12,56.5 12,51.25 16,47.25 26.5,47.25 27.25,48 27.25,53 26,54.25 26,60.25 25.5,60.75
  pour cut-out: 47.5,69 47.5,59.5 79.5,59.5 79.5,69
  text "4" at 7.35,13.725 h2
Multi-Layer:
  pour cut-out: 7.8,15.335 2.025,15.335 2.025,13.335 7.8,13.335

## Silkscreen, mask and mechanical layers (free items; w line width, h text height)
Top Overlay:
  text "J" at 0.75,52.125 h15
  text "MB2274A" at 0.75,48.5 h2.5
Board Layer Stack Bottom Overlay:
  text "E" at 125,49.75 h14
  text "40(BL_K)" at 29.425,41.857 h1.5
  text "H" at 122,38.25 h14
  text "C" at 122,28.5 h13
  text "G" at 108.75,16.5 h14
  text "S" at 121,16.25 h11
  text "I" at 18.75,9.75 h15
  text "F" at 107.25,4.75 h15
Top Solder:
  region: 7.8,15.335 2.025,15.335 2.025,13.335 7.8,13.335
Board Layer Stack Bottom Solder:
  region: 7.8,15.335 2.025,15.335 2.025,13.335 7.8,13.335
M1-Board Shape:
  the board outline again, w0.1
Drill Drawing:
  drawing of 471 lines, arcs and shapes, not listed
  text "THE COMPONENTS WITH PLATED THROUGH HOLE (PTH) MAY BE WELDED (CABLED) IN \"PIN-IN-PASTE\" MODE (IF NECESSARY)" at -9,122.75 h3.5
  text "PCB SPECIFICATIONS :" at -7.964,116.364 h3
  text "A.   MATERIAL :" at -7.964,112.364 h3
  text "FR-4" at 30.536,112.364 h3
  text "TG-170" at 47.036,112.364 h3
  text "X  TG-150" at 65.286,112.364 h3
  text "TG-140" at 81.286,112.364 h3
  text "B.   MATERIAL FAMILY :" at -7.964,109.364 h3
  text "N/A" at 30.536,109.364 h3
  text "C.   SOLDERMASK COLOR :" at -7.964,106.364 h3
  text "GREEN" at 30.536,106.364 h3
  text "X  BLUE" at 47.036,106.364 h3
  text "RED" at 65.286,106.364 h3
  text "BLACK" at 81.286,106.364 h3
  text "D.   SILKSCREEN COLOR :" at -7.964,103.364 h3
  text "X  WHITE" at 30.536,103.364 h3
  text "YELLOW" at 47.036,103.364 h3
  text "BLACK" at 65.286,103.364 h3
  text "Blue ink PANTONE 2955" at 81.286,103.364 h3
  text "E.   SURFACE FINISH :" at -7.964,100.364 h3
  text "X  ENIG" at 30.536,100.364 h3
  text "IMMERSION SILVER" at 47.036,100.364 h3
  text "IMMERSION TIN" at 81.286,100.364 h3
  text "HASL" at 30.536,97.364 h3
  text "HASL (PB-FREE)" at 47.036,97.364 h3
  text "GOLDEN FINGER" at 81.286,97.364 h3
  text "F.   IMPEDANCE CONTROL :" at -7.964,94.364 h3
  text "X  NO" at 30.536,94.364 h3
  text "YES  (SEE IMPEDANCE TABLE FOR DETAIL INFORMATION)" at 47.036,94.364 h3
  text "G.   THROUGH VIA :" at -7.964,91.364 h3
  text "PLUG THE VIAS WHICH ARE COVERED WITH SOLDERMASK ONE OR TWO SIDE." at 30.536,91.364 h3
  text "PLUG MATERIAL :" at 30.536,88.364 h3
  text "X  SOLDERMASK" at 56.036,88.364 h3
  text "NON-CONDUCTIVE EPOXY." at 81.286,88.364 h3
  text "H.   STACK-UP :" at -7.964,85.364 h3
  text "SEE LAYER STACK-UP SEQUENCE FOR OVERALL THICKNESS." at 30.536,85.364 h3
  text "PCB : TYPE 3" at 181.448,85.132 h3
  text "MINIMUM PARAMETERS" at 143.493,85.033 h3
  text "ASPECT-RATIO, AXE Z :" at 181.448,79.632 h3
  text "DEFAULT" at 143.493,79.533 h3
  text "TRACKS : 0.19mm           / GAPS : 0.21mm" at 143.493,73.783 h3
  text "< 6:1 / LEVEL \"A\"" at 181.466,72.884 h3
  text "Layer" at 138.5,63.932 h1.52
  text "Name" at 144.878,63.932 h1.52
  text "Material" at 168.81,63.932 h1.52
  text "Thickness" at 179.895,63.932 h1.52
  text "Constant" at 188.998,63.932 h1.52
  text "Board Layer Stack" at 197.425,63.932 h1.52
  text "Board Layer Stack" at 211.586,63.932 h1.52
  text "Top Overlay" at 144.878,60.884 h1.52
  text "Top Solder" at 144.878,57.836 h1.52
  text "Solder Resist" at 168.81,57.836 h1.52
  text "0,150mm" at 179.895,57.836 h1.52
  text "3.5" at 188.998,57.837 h1.52
  text "1" at 138.5,54.788 h1.52
  text "Top Layer" at 144.878,54.788 h1.52
  text "0,035mm" at 179.895,54.788 h1.52
  text "Dielectric 1" at 144.878,51.74 h1.52
  text "FR-4" at 168.81,51.74 h1.52
  text "0,108mm" at 179.895,51.74 h1.52
  text "3.8" at 188.998,51.741 h1.52
  text "2" at 138.499,48.692 h1.52
  text "Signal Layer 1" at 144.878,48.692 h1.52
  text "0,035mm" at 179.895,48.692 h1.52
  text "Dielectric 2" at 144.878,45.644 h1.52
  text "FR-4" at 168.81,45.644 h1.52
  text "1,134mm" at 179.895,45.644 h1.52
  text "5.1" at 188.998,45.644 h1.52
  text "3" at 138.5,42.596 h1.52
  text "Signal Layer 2" at 144.878,42.596 h1.52
  text "0,035mm" at 179.895,42.596 h1.52
  text "Dielectric 3" at 144.878,39.548 h1.52
  text "FR-4" at 168.81,39.548 h1.52
  text "0,108mm" at 179.895,39.548 h1.52
  text "3.8" at 188.998,39.549 h1.52
  text "4" at 138.5,36.5 h1.52
  text "Bottom Layer" at 144.878,36.5 h1.52
  text "0,035mm" at 179.895,36.5 h1.52
  text "Board Layer Stack Bottom Solder" at 144.878,33.452 h1.52
  text "Solder Resist" at 168.81,33.452 h1.52
  text "0,150mm" at 179.895,33.452 h1.52
  text "3.5" at 188.998,33.453 h1.52
  text "Board Layer Stack Bottom Overlay" at 144.878,30.404 h1.52
  text "Symbol" at 138.804,20.728 h2.16
  text "Count" at 147.26,20.728 h2.16
  text "Hole Size" at 156.821,20.728 h2.16
  text "Plated" at 173.305,20.728 h2.16
  text "Hole Type" at 180.732,20.728 h2.16
  text "Drill Layer Pair" at 191.538,20.728 h2.16
  text "Via/Pad" at 212.026,20.728 h2.16
  text "Pad Shape" at 220.882,20.728 h2.16
  text "Template" at 232.452,20.728 h2.16
  text "1052" at 147.26,16.998 h1.8
  text "0.30mm (11.81mil)" at 156.821,16.998 h1.8
  text "PTH" at 173.305,16.998 h1.8
  text "Round" at 180.732,16.998 h1.8
  text "Top Layer - Bottom Layer" at 191.538,16.998 h1.8
  text "Via" at 212.026,16.998 h1.8
  text "Rounded" at 220.882,16.998 h1.8
  text "v55h30m40" at 232.452,16.998 h1.8
  text "4" at 147.26,13.268 h1.8
  text "4.50mm (177.17mil)" at 156.821,13.268 h1.8
  text "PTH" at 173.305,13.268 h1.8
  text "Round" at 180.732,13.268 h1.8
  text "Top Layer - Bottom Layer" at 191.538,13.268 h1.8
  text "Pad" at 212.026,13.268 h1.8
  text "Rounded" at 220.882,13.268 h1.8
  text "c900h450m910_243987811" at 232.452,13.268 h1.8
  text "1" at 147.26,9.537 h1.8
  text "4.50mm (177.17mil)" at 156.821,9.537 h1.8
  text "NPTH" at 173.305,9.537 h1.8
  text "Slot" at 180.732,9.537 h1.8
  text "Top Layer - Bottom Layer" at 191.538,9.537 h1.8
  text "Pad" at 212.026,9.537 h1.8
  text "Rounded" at 220.882,9.537 h1.8
  text "r8000_450hn450_8000r225" at 232.452,9.537 h1.8
  text "1057 Total" at 147.26,5.807 h1.8
  text "Slot definitions :" at 138.804,3.196 h1.8
  text "Routed Path Length" at 151.079,3.196 h1.8
  text "= Calculated from tool start centre position to tool end centre position." at 166.292,3.196 h1.8
  text "Hole Length" at 151.079,1.704 h1.8
  text "= Routed Path Length + Tool Size = Slot length as defined in the PCB layout" at 160.644,1.704 h1.8

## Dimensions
0,72.5 to 127,72.5 on M2-Board Dimensions
0.5,73 to 0.5,0 on M2-Board Dimensions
